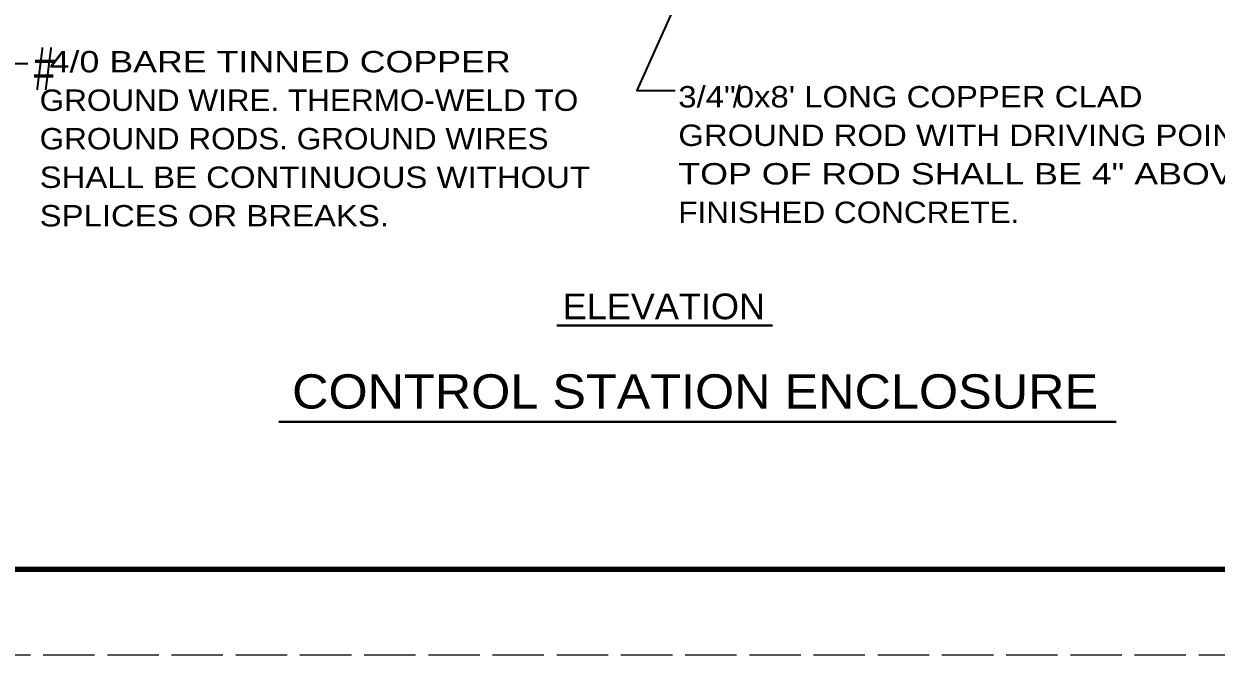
# Model space of a CAD drawing. Extents: x -1 to 679, y 0 to 440.
# Drawn here: x 122.8 to 262.1, y -0.1 to 73.7 of the extents above; entities that cross this region are included whole.
import ezdxf
from ezdxf.enums import TextEntityAlignment as Align

# ---------------------------------------------------------------- set-up
doc = ezdxf.new("R2010")
doc.units = 0
doc.linetypes.add('LONG_DASHED', pattern=[7.5, 6, -1.5])
doc.layers.add('1', color=7, linetype='Continuous', lineweight=53)
doc.layers.add('61', color=7, linetype='Continuous', lineweight=35)

msp = doc.modelspace()

# ---------------------------------------------------------------- linework, layer by layer
at = {"layer": '1', "lineweight": 40}
for p, q in [((185.076, 38.45), (210.265, 38.45)), ((152.614, 27.163), (250.42, 27.163))]:
    msp.add_line(p, q, dxfattribs=at)
at = {"layer": '1', "lineweight": 35}
for points in [[(116.441, 80.358), (115.517, 69.054), (123.261, 69.054)], [(199.849, 77.986), (194.409, 65.893), (198.894, 65.893)]]:
    msp.add_lwpolyline(points, dxfattribs=at)
at = {"layer": '61', "lineweight": 158}
msp.add_line((667.629, 9.921), (28.569, 9.941), dxfattribs=at)
at = {"layer": '61', "linetype": 'LONG_DASHED', "lineweight": 13}
msp.add_line((678.569, -0.059), (-1.491, -0.079), dxfattribs=at)

# ---------------------------------------------------------------- texts
at = {"layer": '1'}
for s, height, width, p in [('#', 5, 0.65, (125.188, 65.959)), ('CONTROL STATION ENCLOSURE', 4, 1.1, (201.225, 28.733))]:
    msp.add_text(s, height=height, dxfattribs=dict(at, width=width)).set_placement(p, align=Align.CENTER)
for s, height, width, p in [(' 4/0 BARE TINNED COPPER', 2.5, 1.25, (124.658, 68.01)), ('GROUND WIRE. THERMO-WELD TO', 2.5, 1.1, (124.658, 63.511)), ('3/4"0x8\' LONG COPPER CLAD', 2.5, 1.15, (199.264, 63.911)), ('GROUND RODS. GROUND WIRES', 2.5, 1.1, (124.658, 59.011)), ('GROUND ROD WITH DRIVING POINT.', 2.5, 1.15, (199.264, 59.411)), ('TOP OF ROD SHALL BE 4" ABOVE', 2.5, 1.25, (199.264, 54.911)), ('SHALL BE CONTINUOUS WITHOUT', 2.5, 1.15, (124.658, 54.511)), ('FINISHED CONCRETE.', 2.5, 1.1, (199.264, 50.411)), ('SPLICES OR BREAKS.', 2.5, 1.15, (124.658, 50.011)), ('ELEVATION', 3, 1.05, (185.759, 39.172))]:
    msp.add_text(s, height=height, dxfattribs=dict(at, width=width)).set_placement(p)
msp.add_text('/', height=2.5, dxfattribs=at).set_placement((206.104, 63.94), align=Align.CENTER)

doc.saveas('drawing.dxf')
